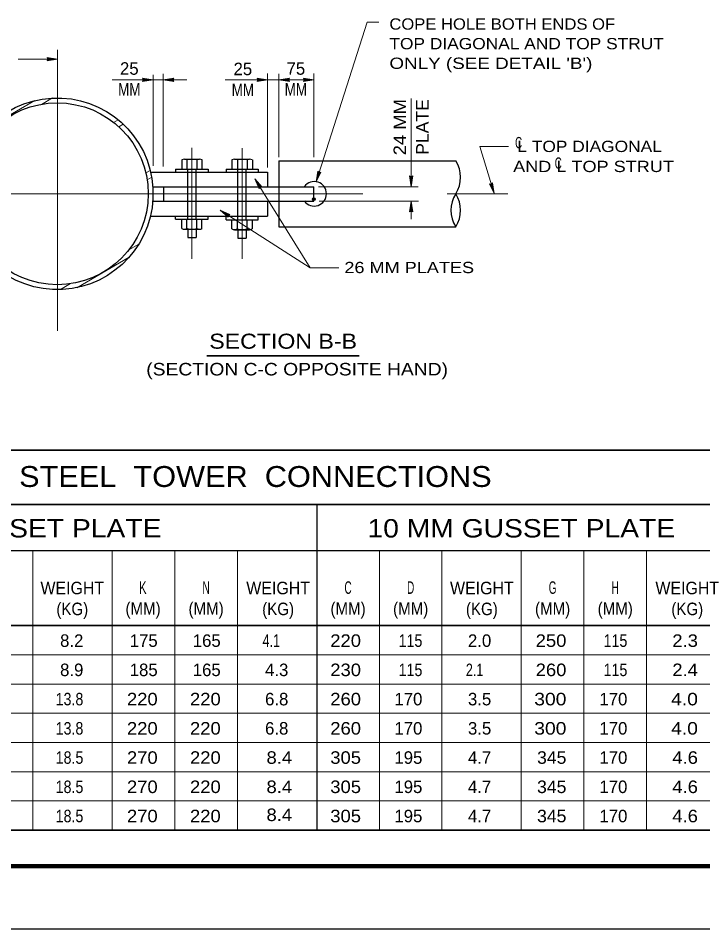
# Model space of a CAD drawing. Extents: x 312601.858 to 312602.699, y 144420.109 to 144420.704.
# Drawn here: x 312602.1142 to 312602.2782, y 144420.1095 to 144420.3275 of the extents above; entities that cross this region are included whole.
import ezdxf
from ezdxf.enums import TextEntityAlignment as Align

# ---------------------------------------------------------------- set-up
doc = ezdxf.new("R2010")
doc.units = 0
doc.header["$LTSCALE"] = 0.0012
doc.header["$PDMODE"] = 32
doc.header["$PDSIZE"] = 0.0006
doc.linetypes.add('DOT_DASHED', pattern=[7.7, 5, -1.2, 0.3, -1.2])
doc.linetypes.add('MEDIUM_DASHED', pattern=[4.5, 3, -1.5])
for name, color, linetype, lineweight in [('1', 7, 'Continuous', 25), ('2', 7, 'Continuous', 13), ('39', 7, 'Continuous', 13)]:
    doc.layers.add(name, color=color, linetype=linetype, lineweight=lineweight)

msp = doc.modelspace()

# ---------------------------------------------------------------- hatches: boundary and pattern name
at = {"layer": '39'}
for points in [[(312602.1213, 144420.3177), (312602.1211, 144420.3181), (312602.1236, 144420.3177), (312602.1211, 144420.3173)], [(312602.1442, 144420.3128), (312602.144, 144420.3132), (312602.1465, 144420.3128), (312602.144, 144420.3124)], [(312602.1512, 144420.3128), (312602.1515, 144420.3124), (312602.1489, 144420.3128), (312602.1515, 144420.3132)], [(312602.1716, 144420.3128), (312602.1714, 144420.3132), (312602.1739, 144420.3128), (312602.1714, 144420.3124)], [(312602.1716, 144420.3128), (312602.1714, 144420.3132), (312602.1739, 144420.3128), (312602.1714, 144420.3124)], [(312602.1789, 144420.3128), (312602.1792, 144420.3124), (312602.1766, 144420.3128), (312602.1792, 144420.3132)], [(312602.1789, 144420.3128), (312602.1792, 144420.3124), (312602.1766, 144420.3128), (312602.1792, 144420.3132)], [(312602.1827, 144420.3128), (312602.1825, 144420.3132), (312602.185, 144420.3128), (312602.1825, 144420.3124)], [(312602.1827, 144420.3128), (312602.1825, 144420.3132), (312602.185, 144420.3128), (312602.1825, 144420.3124)], [(312602.1863, 144420.2906), (312602.1867, 144420.2907), (312602.1856, 144420.2884), (312602.186, 144420.2909)], [(312602.1721, 144420.2871), (312602.1719, 144420.2867), (312602.1709, 144420.2891), (312602.1726, 144420.2871)], [(312602.1721, 144420.2871), (312602.1719, 144420.2867), (312602.1709, 144420.2891), (312602.1726, 144420.2871)], [(312602.2083, 144420.2895), (312602.2087, 144420.2898), (312602.2083, 144420.2872), (312602.2079, 144420.2898)], [(312602.2275, 144420.2878), (312602.2278, 144420.2881), (312602.2282, 144420.2856), (312602.2271, 144420.2879)], [(312602.2083, 144420.2814), (312602.2079, 144420.2812), (312602.2083, 144420.2837), (312602.2087, 144420.2812)], [(312602.1646, 144420.2803), (312602.1645, 144420.2799), (312602.1626, 144420.2816), (312602.1649, 144420.2805)]]:
    msp.add_hatch(color=256, dxfattribs=at).paths.add_polyline_path(points)

# ---------------------------------------------------------------- linework, layer by layer
at = {"layer": '1', "lineweight": 13}
for p, q in [((312602.1236, 144420.32), (312602.1236, 144420.313)), ((312602.1236, 144420.3177), (312602.1142, 144420.3177)), ((312602.1465, 144420.2922), (312602.1465, 144420.314)), ((312602.1489, 144420.3142), (312602.1489, 144420.292)), ((312602.1489, 144420.3128), (312602.1546, 144420.3128)), ((312602.1638, 144420.3128), (312602.1739, 144420.3128)), ((312602.1739, 144420.3143), (312602.1739, 144420.2918)), ((312602.1766, 144420.3142), (312602.1766, 144420.2943)), ((312602.185, 144420.3143), (312602.185, 144420.2943)), ((312602.1198, 144420.3069), (312602.1224, 144420.3085)), ((312602.2083, 144420.3083), (312602.2083, 144420.2872)), ((312602.1069, 144420.3013), (312602.1182, 144420.3078)), ((312602.137, 144420.3026), (312602.1381, 144420.3032)), ((312602.1383, 144420.3015), (312602.1393, 144420.3022)), ((312602.2248, 144420.2968), (312602.2316, 144420.2968)), ((312602.2248, 144420.2968), (312602.2282, 144420.2856)), ((312602.1448, 144420.2905), (312602.1458, 144420.2911)), ((312602.1451, 144420.2888), (312602.1462, 144420.2895)), ((312602.1861, 144420.2872), (312602.21, 144420.2872)), ((312602.2169, 144420.2855), (312602.2315, 144420.2855)), ((312602.1863, 144420.2837), (312602.2101, 144420.2837)), ((312602.2083, 144420.2837), (312602.2083, 144420.2794)), ((312602.1841, 144420.2678), (312602.1626, 144420.2816)), ((312602.154, 144420.277), (312602.1576, 144420.277)), ((312602.1407, 144420.2721), (312602.1431, 144420.2734)), ((312602.1282, 144420.263), (312602.1408, 144420.2703)), ((312602.1243, 144420.2626), (312602.1267, 144420.264))]:
    msp.add_line(p, q, dxfattribs=at)
at = {"layer": '1', "linetype": 'DOT_DASHED', "lineweight": 13}
for p, q in [((312602.1236, 144420.3173), (312602.1236, 144420.2527)), ((312602.1558, 144420.2699), (312602.1558, 144420.2965)), ((312602.1678, 144420.2699), (312602.1678, 144420.2964)), ((312602.0967, 144420.2855), (312602.2188, 144420.2855))]:
    msp.add_line(p, q, dxfattribs=at)
at = {"layer": '1'}
for p, q in [((312602.1534, 144420.2936), (312602.1534, 144420.2914)), ((312602.154, 144420.2938), (312602.1576, 144420.2938)), ((312602.154, 144420.2938), (312602.1576, 144420.2938)), ((312602.1546, 144420.2936), (312602.1546, 144420.2914)), ((312602.157, 144420.2936), (312602.157, 144420.2914)), ((312602.1582, 144420.2936), (312602.1582, 144420.2914)), ((312602.1654, 144420.2936), (312602.1654, 144420.2914)), ((312602.166, 144420.2938), (312602.1696, 144420.2938)), ((312602.166, 144420.2938), (312602.1696, 144420.2938)), ((312602.1667, 144420.2936), (312602.1667, 144420.2914)), ((312602.169, 144420.2936), (312602.169, 144420.2914)), ((312602.1703, 144420.2936), (312602.1703, 144420.2914)), ((312602.1766, 144420.2934), (312602.219, 144420.2934)), ((312602.1766, 144420.2934), (312602.1766, 144420.2872)), ((312602.1459, 144420.2907), (312602.1739, 144420.2907)), ((312602.1519, 144420.2914), (312602.1519, 144420.2907)), ((312602.164, 144420.2914), (312602.164, 144420.2907)), ((312602.1739, 144420.2907), (312602.1739, 144420.2872)), ((312602.1464, 144420.2872), (312602.185, 144420.2872)), ((312602.149, 144420.2872), (312602.149, 144420.2836)), ((312602.185, 144420.2837), (312602.185, 144420.2872)), ((312602.185, 144420.2837), (312602.185, 144420.2872)), ((312602.185, 144420.2837), (312602.185, 144420.2872)), ((312602.1465, 144420.2837), (312602.185, 144420.2837)), ((312602.1739, 144420.2837), (312602.1739, 144420.2801)), ((312602.1459, 144420.2801), (312602.1739, 144420.2801)), ((312602.1519, 144420.2794), (312602.1519, 144420.2801)), ((312602.164, 144420.2793), (312602.164, 144420.28)), ((312602.1534, 144420.2772), (312602.1534, 144420.2794)), ((312602.1546, 144420.2772), (312602.1546, 144420.2794)), ((312602.157, 144420.2772), (312602.157, 144420.2794)), ((312602.1582, 144420.2772), (312602.1582, 144420.2794)), ((312602.1654, 144420.2771), (312602.1654, 144420.2793)), ((312602.1667, 144420.2771), (312602.1667, 144420.2793)), ((312602.169, 144420.2771), (312602.169, 144420.2793)), ((312602.1703, 144420.2771), (312602.1703, 144420.2793)), ((312602.154, 144420.277), (312602.1576, 144420.277)), ((312602.1548, 144420.277), (312602.1548, 144420.275)), ((312602.1568, 144420.277), (312602.1568, 144420.275)), ((312602.166, 144420.2769), (312602.1696, 144420.2769)), ((312602.166, 144420.2769), (312602.1696, 144420.2769)), ((312602.1668, 144420.2769), (312602.1668, 144420.2749)), ((312602.1688, 144420.277), (312602.1688, 144420.2749)), ((312602.1548, 144420.275), (312602.1568, 144420.275)), ((312602.1668, 144420.2749), (312602.1688, 144420.2749))]:
    msp.add_line(p, q, dxfattribs=at)
at = {"layer": '1', "linetype": 'MEDIUM_DASHED'}
for p, q in [((312602.1548, 144420.2795), (312602.1548, 144420.2913)), ((312602.1568, 144420.2795), (312602.1568, 144420.2914)), ((312602.1668, 144420.2794), (312602.1668, 144420.2913)), ((312602.1688, 144420.2794), (312602.1688, 144420.2913)), ((312602.1766, 144420.2872), (312602.1766, 144420.2837))]:
    msp.add_line(p, q, dxfattribs=at)
at = {"layer": '1', "lineweight": 13}
for points in [[(312602.2006, 144420.3266), (312602.1978, 144420.3266), (312602.1856, 144420.2884)], [(312602.1367, 144420.3128), (312602.1465, 144420.3128), (312602.1489, 144420.3128)], [(312602.1739, 144420.3128), (312602.1766, 144420.3128), (312602.185, 144420.3128)], [(312602.191, 144420.2678), (312602.1841, 144420.2678), (312602.1709, 144420.2891)]]:
    msp.add_lwpolyline(points, dxfattribs=at)
at = {"layer": '1'}
for points in [[(312602.1519, 144420.2914), (312602.1597, 144420.2914), (312602.1597, 144420.2907)], [(312602.164, 144420.2914), (312602.1717, 144420.2914), (312602.1717, 144420.2907)], [(312602.1766, 144420.2837), (312602.1766, 144420.2776), (312602.219, 144420.2776)], [(312602.1519, 144420.2794), (312602.1597, 144420.2794), (312602.1597, 144420.2801)], [(312602.164, 144420.2793), (312602.1717, 144420.2793), (312602.1717, 144420.28)]]:
    msp.add_lwpolyline(points, dxfattribs=at)
msp.add_circle((312602.12356, 144420.2855), 0.02178, dxfattribs=at)
for centre, radius, start, end in [((312602.12356, 144420.2855), 0.02295, 3.25763, 2.95461), ((312602.154, 144420.292588), 0.001192, 58.10921, 121.89079), ((312602.153985, 144420.292535), 0.001245, 58.79949, 89.30972), ((312602.1558, 144420.289888), 0.003893, 72.50768, 107.49232), ((312602.1558, 144420.289888), 0.003893, 72.78254, 107.49232), ((312602.1576, 144420.292588), 0.001192, 58.10921, 121.89079), ((312602.157615, 144420.292535), 0.001245, 90.69028, 121.20051), ((312602.16602, 144420.292588), 0.001192, 58.10921, 121.89079), ((312602.166005, 144420.292535), 0.001245, 58.79949, 89.30972), ((312602.16782, 144420.289888), 0.003893, 72.78254, 107.49232), ((312602.16962, 144420.292588), 0.001192, 58.10921, 121.89079), ((312602.169635, 144420.292535), 0.001245, 90.69028, 121.20051), ((312602.212877, 144420.28946), 0.007275, 327.02071, 32.97929), ((312602.1851, 144420.2855), 0.002927, 216.15819, 143.97263), ((312602.225083, 144420.28154), 0.007275, 147.02071, 212.97929), ((312602.212877, 144420.28154), 0.007275, 327.02071, 32.97929), ((312602.154, 144420.278213), 0.001192, 238.10921, 301.89079), ((312602.1558, 144420.280912), 0.003893, 252.50768, 287.49232), ((312602.1576, 144420.278213), 0.001192, 238.10921, 301.89079), ((312602.16602, 144420.278113), 0.001192, 238.10921, 301.89079), ((312602.166005, 144420.278165), 0.001245, 270.69028, 301.20051), ((312602.16782, 144420.280812), 0.003893, 252.50768, 287.49232), ((312602.16782, 144420.280812), 0.003893, 252.50768, 287.21746), ((312602.16962, 144420.278113), 0.001192, 238.10921, 301.89079), ((312602.169635, 144420.278165), 0.001245, 238.79949, 269.30972)]:
    msp.add_arc(centre, radius, start, end, dxfattribs=at)
at = {"layer": '1', "lineweight": 13}
for centre, radius, start, end in [((312602.16782, 144420.289888), 0.003893, 72.50768, 107.49232), ((312602.153985, 144420.278265), 0.001245, 270.69028, 301.20051), ((312602.1558, 144420.280912), 0.003893, 252.50768, 287.21746), ((312602.157615, 144420.278265), 0.001245, 238.79949, 269.30972)]:
    msp.add_arc(centre, radius, start, end, dxfattribs=at)
at = {"layer": '1'}
msp.add_point((312602.185, 144420.2842), dxfattribs=at)
at = {"layer": '2', "lineweight": 35}
for p, q in [((312602.1594, 144420.2467), (312602.1959, 144420.2467)), ((312602.0147, 144420.2241), (312602.3284, 144420.2241)), ((312602.0147, 144420.2111), (312602.3287, 144420.2111)), ((312602.0147, 144420.1821), (312602.3287, 144420.1821)), ((312602.0147, 144420.1331), (312602.3287, 144420.1331))]:
    msp.add_line(p, q, dxfattribs=at)
at = {"layer": '2', "lineweight": 25}
for p, q in [((312602.1857, 144420.2111), (312602.1857, 144420.1331)), ((312602.0387, 144420.2001), (312602.3287, 144420.2001))]:
    msp.add_line(p, q, dxfattribs=at)
at = {"layer": '2'}
for p, q in [((312602.1177, 144420.2001), (312602.1177, 144420.1331)), ((312602.1367, 144420.2001), (312602.1367, 144420.1331)), ((312602.1517, 144420.2001), (312602.1517, 144420.1331)), ((312602.1667, 144420.2001), (312602.1667, 144420.1331)), ((312602.2007, 144420.2001), (312602.2007, 144420.1331)), ((312602.2157, 144420.2001), (312602.2157, 144420.1331)), ((312602.2347, 144420.2001), (312602.2347, 144420.1331)), ((312602.2497, 144420.2001), (312602.2497, 144420.1331)), ((312602.2647, 144420.2001), (312602.2647, 144420.1331)), ((312602.0147, 144420.1751), (312602.3287, 144420.1751)), ((312602.0147, 144420.1681), (312602.3287, 144420.1681)), ((312602.0147, 144420.1611), (312602.3284, 144420.1611)), ((312602.0147, 144420.1541), (312602.3287, 144420.1541)), ((312602.0147, 144420.1471), (312602.3287, 144420.1471)), ((312602.0147, 144420.1401), (312602.3287, 144420.1401))]:
    msp.add_line(p, q, dxfattribs=at)
at = {"layer": '39', "lineweight": 158}
msp.add_line((312601.9088, 144420.1245), (312602.6838, 144420.1245), dxfattribs=at)
at = {"layer": '39', "lineweight": 25}
msp.add_line((312601.8578, 144420.1095), (312602.6988, 144420.1095), dxfattribs=at)
at = {"layer": '39'}
for points in [[(312602.1213, 144420.3177), (312602.1211, 144420.3181), (312602.1236, 144420.3177), (312602.1211, 144420.3173)], [(312602.1442, 144420.3128), (312602.144, 144420.3132), (312602.1465, 144420.3128), (312602.144, 144420.3124)], [(312602.1512, 144420.3128), (312602.1515, 144420.3124), (312602.1489, 144420.3128), (312602.1515, 144420.3132)], [(312602.1716, 144420.3128), (312602.1714, 144420.3132), (312602.1739, 144420.3128), (312602.1714, 144420.3124)], [(312602.1716, 144420.3128), (312602.1714, 144420.3132), (312602.1739, 144420.3128), (312602.1714, 144420.3124)], [(312602.1789, 144420.3128), (312602.1792, 144420.3124), (312602.1766, 144420.3128), (312602.1792, 144420.3132)], [(312602.1789, 144420.3128), (312602.1792, 144420.3124), (312602.1766, 144420.3128), (312602.1792, 144420.3132)], [(312602.1827, 144420.3128), (312602.1825, 144420.3132), (312602.185, 144420.3128), (312602.1825, 144420.3124)], [(312602.1827, 144420.3128), (312602.1825, 144420.3132), (312602.185, 144420.3128), (312602.1825, 144420.3124)], [(312602.1863, 144420.2906), (312602.1867, 144420.2907), (312602.1856, 144420.2884), (312602.186, 144420.2909)], [(312602.1721, 144420.2871), (312602.1719, 144420.2867), (312602.1709, 144420.2891), (312602.1726, 144420.2871)], [(312602.1721, 144420.2871), (312602.1719, 144420.2867), (312602.1709, 144420.2891), (312602.1726, 144420.2871)], [(312602.2083, 144420.2895), (312602.2087, 144420.2898), (312602.2083, 144420.2872), (312602.2079, 144420.2898)], [(312602.2275, 144420.2878), (312602.2278, 144420.2881), (312602.2282, 144420.2856), (312602.2271, 144420.2879)], [(312602.2083, 144420.2814), (312602.2079, 144420.2812), (312602.2083, 144420.2837), (312602.2087, 144420.2812)], [(312602.1646, 144420.2803), (312602.1645, 144420.2799), (312602.1626, 144420.2816), (312602.1649, 144420.2805)]]:
    msp.add_lwpolyline(points, close=True, dxfattribs=at)

# ---------------------------------------------------------------- texts
at = {"layer": '2'}
for s, width, p in [('COPE HOLE BOTH ENDS OF', 1.1, (312602.2031, 144420.3248)), ('TOP DIAGONAL AND TOP STRUT', 1.15, (312602.2031, 144420.3201)), ("ONLY (SEE DETAIL 'B')", 1.25, (312602.2031, 144420.3154))]:
    msp.add_text(s, height=0.0027, dxfattribs=dict(at, width=width)).set_placement(p)
for s, p in [('25', (312602.1408, 144420.314)), ('25', (312602.168, 144420.3139)), ('75', (312602.1807, 144420.314))]:
    msp.add_text(s, height=0.003, dxfattribs=at).set_placement(p, align=Align.CENTER)
for s, height, width, p in [('MM', 0.003, 0.8, (312602.1408, 144420.309)), ('MM', 0.003, 0.8, (312602.168, 144420.3089)), ('MM', 0.003, 0.8, (312602.1807, 144420.309)), ('C', 0.0027, 0.65, (312602.23405, 144420.2964)), ('L TOP DIAGONAL', 0.0027, 1.15, (312602.25105, 144420.2955)), ('AND L TOP STRUT', 0.0027, 1.2, (312602.252, 144420.2907)), ('C', 0.0027, 0.65, (312602.24355, 144420.2915)), ('26 MM PLATES', 0.0027, 1.2, (312602.20785, 144420.2665)), ('SECTION B-B', 0.0036, 1.15, (312602.17765, 144420.2484)), ('(SECTION C-C OPPOSITE HAND)', 0.003, 1.15, (312602.181, 144420.242)), ('STEEL  TOWER  CONNECTIONS', 0.005, 1.1, (312602.171, 144420.2153)), ('18 MM GUSSET PLATE', 0.0044, 1.15, (312602.11165, 144420.2032)), ('10 MM GUSSET PLATE', 0.0044, 1.15, (312602.2347, 144420.2032)), ('WEIGHT', 0.003, 0.95, (312602.12715, 144420.1896)), ('K', 0.003, 0.65, (312602.14405, 144420.1897)), ('N', 0.003, 0.6, (312602.1592, 144420.1897)), ('WEIGHT', 0.003, 0.95, (312602.17645, 144420.1896)), ('C', 0.003, 0.6, (312602.1932, 144420.1897)), ('D', 0.003, 0.6, (312602.2082, 144420.1897)), ('WEIGHT', 0.003, 0.95, (312602.22525, 144420.1896)), ('G', 0.003, 0.6, (312602.2422, 144420.1897)), ('H', 0.003, 0.6, (312602.25715, 144420.1897)), ('WEIGHT', 0.003, 0.95, (312602.27445, 144420.1896)), ('(KG)', 0.003, 0.9, (312602.12715, 144420.1846)), ('(MM)', 0.003, 0.9, (312602.1441, 144420.1847)), ('(MM)', 0.003, 0.9, (312602.1592, 144420.1847)), ('(KG)', 0.003, 0.9, (312602.17645, 144420.1846)), ('(MM)', 0.003, 0.9, (312602.1932, 144420.1847)), ('(MM)', 0.003, 0.9, (312602.2082, 144420.1847)), ('(KG)', 0.003, 0.9, (312602.22525, 144420.1846)), ('(MM)', 0.003, 0.9, (312602.2422, 144420.1847)), ('(MM)', 0.003, 0.9, (312602.2572, 144420.1847)), ('(KG)', 0.003, 0.9, (312602.27445, 144420.1846))]:
    msp.add_text(s, height=height, dxfattribs=dict(at, width=width)).set_placement(p, align=Align.CENTER)
for s, width, p in [('PLATE', 1.05, (312602.2125, 144420.3015)), ('24 MM', 1.1, (312602.2071, 144420.30145))]:
    msp.add_text(s, height=0.003, rotation=90, dxfattribs=dict(at, width=width)).set_placement(p, align=Align.CENTER)
for s, p in [('8.2', (312602.1298, 144420.177)), ('175', (312602.1476, 144420.177)), ('165', (312602.1627, 144420.177)), ('2.0', (312602.2275, 144420.177)), ('8.9', (312602.1298, 144420.17)), ('185', (312602.1476, 144420.17)), ('165', (312602.1627, 144420.17)), ('4.3', (312602.1789, 144420.17)), ('6.8', (312602.1789, 144420.163)), ('170', (312602.211, 144420.163)), ('3.5', (312602.2275, 144420.163)), ('170', (312602.2601, 144420.163)), ('6.8', (312602.1789, 144420.156)), ('170', (312602.211, 144420.156)), ('3.5', (312602.2275, 144420.156)), ('170', (312602.2601, 144420.156)), ('195', (312602.211, 144420.149)), ('4.7', (312602.2275, 144420.149)), ('170', (312602.2601, 144420.149)), ('195', (312602.211, 144420.142)), ('4.7', (312602.2275, 144420.142)), ('170', (312602.2601, 144420.142)), ('195', (312602.211, 144420.135)), ('4.7', (312602.2275, 144420.135)), ('170', (312602.2601, 144420.135))]:
    msp.add_text(s, height=0.003, dxfattribs=at).set_placement(p, align=Align.RIGHT)
for s, width, p in [('4.1', 0.75, (312602.1769, 144420.177)), ('220', 1.1, (312602.1963, 144420.177)), ('115', 0.85, (312602.211, 144420.177)), ('250', 1.1, (312602.2455, 144420.177)), ('115', 0.85, (312602.2601, 144420.177)), ('2.3', 1.1, (312602.277, 144420.177)), ('230', 1.1, (312602.1963, 144420.17)), ('115', 0.85, (312602.211, 144420.17)), ('2.1', 0.75, (312602.2256, 144420.17)), ('260', 1.1, (312602.2455, 144420.17)), ('115', 0.85, (312602.2601, 144420.17)), ('2.4', 1.1, (312602.277, 144420.17)), ('13.8', 0.85, (312602.1298, 144420.163)), ('220', 1.1, (312602.1476, 144420.163)), ('220', 1.1, (312602.1627, 144420.163)), ('260', 1.1, (312602.1963, 144420.163)), ('300', 1.15, (312602.2455, 144420.163)), ('4.0', 1.15, (312602.277, 144420.163)), ('13.8', 0.85, (312602.1298, 144420.156)), ('220', 1.1, (312602.1476, 144420.156)), ('220', 1.1, (312602.1627, 144420.156)), ('260', 1.1, (312602.1963, 144420.156)), ('300', 1.15, (312602.2455, 144420.156)), ('4.0', 1.15, (312602.277, 144420.156)), ('18.5', 0.85, (312602.1298, 144420.149)), ('270', 1.1, (312602.1476, 144420.149)), ('220', 1.1, (312602.1627, 144420.149)), ('8.4', 1.1, (312602.1798, 144420.149)), ('305', 1.1, (312602.1963, 144420.149)), ('345', 1.05, (312602.2455, 144420.149)), ('4.6', 1.1, (312602.277, 144420.149)), ('18.5', 0.85, (312602.1298, 144420.142)), ('270', 1.1, (312602.1476, 144420.142)), ('220', 1.1, (312602.1627, 144420.142)), ('8.4', 1.1, (312602.1798, 144420.142)), ('305', 1.1, (312602.1963, 144420.142)), ('345', 1.05, (312602.2455, 144420.142)), ('4.6', 1.1, (312602.277, 144420.142)), ('18.5', 0.85, (312602.1298, 144420.135)), ('270', 1.1, (312602.1476, 144420.135)), ('220', 1.1, (312602.1627, 144420.135)), ('8.4', 1.1, (312602.1798, 144420.1353)), ('305', 1.1, (312602.1963, 144420.135)), ('345', 1.05, (312602.2455, 144420.135)), ('4.6', 1.1, (312602.277, 144420.135))]:
    msp.add_text(s, height=0.003, dxfattribs=dict(at, width=width)).set_placement(p, align=Align.RIGHT)

doc.saveas('drawing.dxf')
